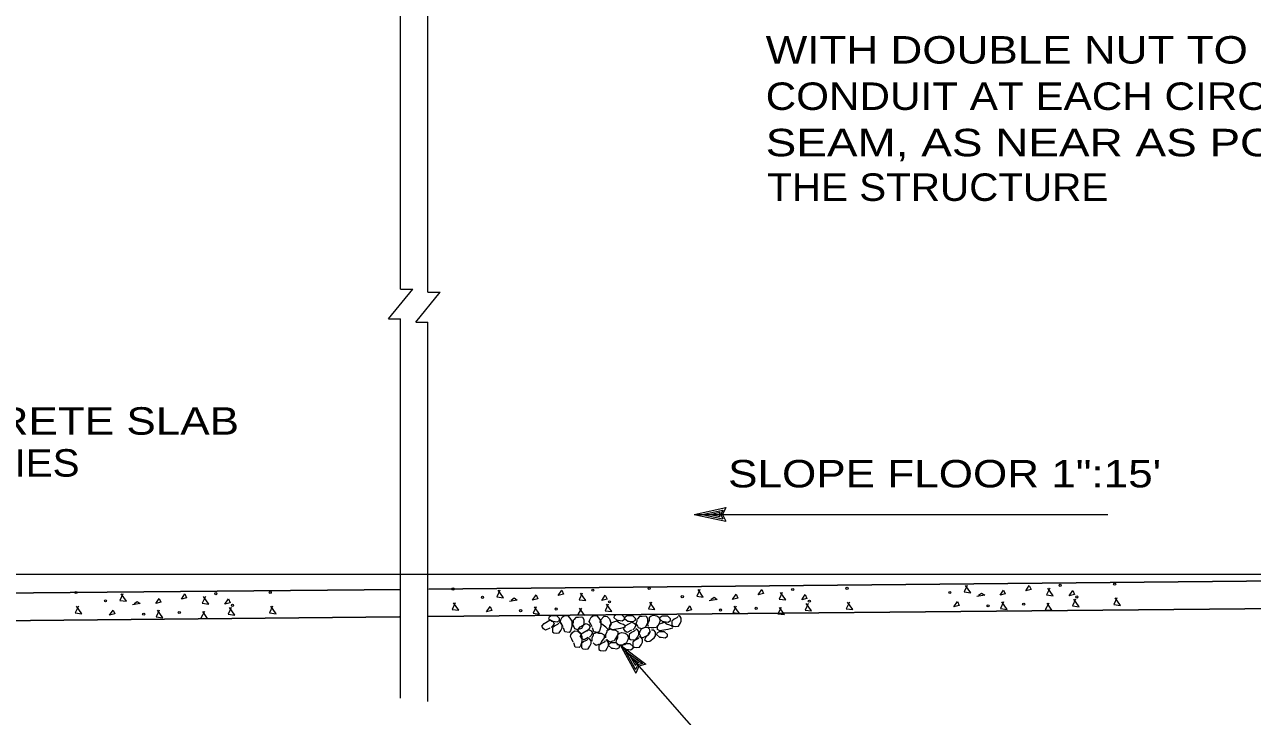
# Model space of a CAD drawing. Extents: x -22.3 to 19.7, y -11.8 to 18.2.
# Drawn here: x -12.72 to -7.13, y -8.18 to -5.03 of the extents above; entities that cross this region are included whole.
import ezdxf
from ezdxf.enums import TextEntityAlignment as Align

# ---------------------------------------------------------------- set-up
doc = ezdxf.new("R2010")
doc.units = 0
doc.header["$LTSCALE"] = 0.05
doc.layers.add('1', color=7, linetype='Continuous', lineweight=13)
doc.layers.add('2', color=7, linetype='Continuous', lineweight=13)

msp = doc.modelspace()

# ---------------------------------------------------------------- linework, layer by layer
at = {"layer": '1'}
for p, q in [((-11.00842, -6.23369), (-11.00842, -4.79569)), ((-10.88342, -6.24869), (-10.88342, -4.81069)), ((-11.06242, -6.36969), (-10.95242, -6.23369)), ((-11.00842, -6.23369), (-10.95242, -6.23369)), ((-10.93742, -6.38469), (-10.82742, -6.24869)), ((-10.88342, -6.24869), (-10.82742, -6.24869)), ((-11.06242, -6.36969), (-11.00842, -6.36969)), ((-11.00842, -8.09569), (-11.00842, -6.36969)), ((-10.93742, -6.38469), (-10.88342, -6.38469)), ((-10.88342, -8.11069), (-10.88342, -6.38469)), ((-9.67142, -7.25969), (-9.52742, -7.22869)), ((-9.67142, -7.25969), (-9.52742, -7.29069)), ((-9.67142, -7.25969), (-7.78742, -7.25969)), ((-9.63442, -7.25969), (-9.54042, -7.23969)), ((-9.63442, -7.25969), (-9.54042, -7.27969)), ((-9.59842, -7.25969), (-9.55342, -7.24969)), ((-9.59842, -7.25969), (-9.55342, -7.26869)), ((-9.55342, -7.24969), (-9.55742, -7.25969)), ((-9.55742, -7.25969), (-9.55342, -7.26869)), ((-9.54042, -7.23969), (-9.54942, -7.25969)), ((-9.54942, -7.25969), (-9.54042, -7.27969)), ((-5.69442, -7.53269), (-18.28242, -7.53269)), ((-10.00842, -7.85269), (-9.89042, -7.94069)), ((-10.00842, -7.85269), (-9.93642, -7.98169)), ((-9.98442, -7.88069), (-9.90642, -7.93769)), ((-9.98442, -7.88069), (-9.93742, -7.96469)), ((-9.96042, -7.90769), (-9.93742, -7.94769)), ((-9.96042, -7.90769), (-9.92342, -7.93469)), ((-9.92342, -7.93469), (-9.93342, -7.93869)), ((-9.90642, -7.93769), (-9.92742, -7.94469)), ((-9.93342, -7.93869), (-9.93742, -7.94769)), ((-9.92742, -7.94469), (-9.93742, -7.96469))]:
    msp.add_line(p, q, dxfattribs=at)
at = {"layer": '1', "lineweight": 25}
for p, q in [((-10.87842, -7.59969), (-3.99142, -7.53369)), ((-16.90342, -7.65769), (-11.00642, -7.60069)), ((-10.88242, -7.72469), (-3.99142, -7.65869)), ((-16.90242, -7.78269), (-11.01242, -7.72569))]:
    msp.add_line(p, q, dxfattribs=at)
at = {"layer": '1'}
for points in [[(-9.52742, -7.22869), (-9.54142, -7.25969), (-9.52742, -7.29069)], [(-10.32842, -7.77669), (-10.34742, -7.78669), (-10.35742, -7.78069), (-10.36442, -7.76869), (-10.35342, -7.75569), (-10.32642, -7.73969), (-10.31442, -7.74569), (-10.30842, -7.75569), (-10.31642, -7.76869), (-10.32242, -7.77469)], [(-10.28742, -7.75469), (-10.29342, -7.76069), (-10.30542, -7.76669), (-10.31642, -7.77569), (-10.31642, -7.78569), (-10.31642, -7.79369), (-10.30942, -7.79869), (-10.29742, -7.80069), (-10.28542, -7.79869), (-10.27842, -7.78769), (-10.27242, -7.77569), (-10.27242, -7.76269), (-10.27842, -7.75469), (-10.28542, -7.75069)], [(-10.26742, -7.77169), (-10.27342, -7.75869), (-10.28042, -7.74669), (-10.27842, -7.73869), (-10.27142, -7.72769), (-10.26142, -7.71969), (-10.24642, -7.72169), (-10.23642, -7.73169), (-10.22842, -7.74469), (-10.22842, -7.76969), (-10.23442, -7.78969), (-10.24042, -7.79669), (-10.25942, -7.79469), (-10.26542, -7.77569)], [(-10.22142, -7.73869), (-10.22142, -7.75169), (-10.22642, -7.75969), (-10.21942, -7.77169), (-10.21542, -7.77869), (-10.20142, -7.78269), (-10.18242, -7.77669), (-10.17242, -7.75769), (-10.17242, -7.74769), (-10.17242, -7.73869), (-10.17842, -7.72869), (-10.18442, -7.72669), (-10.19742, -7.72869), (-10.20942, -7.72869), (-10.21942, -7.73869)], [(-10.16442, -7.79269), (-10.18342, -7.80269), (-10.19342, -7.79669), (-10.20042, -7.78469), (-10.18942, -7.77169), (-10.16242, -7.75569), (-10.15042, -7.76169), (-10.14442, -7.77169), (-10.15242, -7.78469), (-10.15842, -7.79069)], [(-10.13542, -7.77169), (-10.14142, -7.75869), (-10.14842, -7.74669), (-10.14642, -7.73869), (-10.13942, -7.72769), (-10.12942, -7.71969), (-10.11442, -7.72169), (-10.10442, -7.73169), (-10.09642, -7.74469), (-10.09642, -7.76969), (-10.10242, -7.78969), (-10.10842, -7.79669), (-10.12742, -7.79469), (-10.13342, -7.77569)], [(-10.06042, -7.78469), (-10.07242, -7.77269), (-10.09142, -7.75969), (-10.09942, -7.74969), (-10.09742, -7.74069), (-10.08142, -7.72269), (-10.06642, -7.72469), (-10.05642, -7.73469), (-10.05042, -7.75369), (-10.04842, -7.75969), (-10.06042, -7.78069)], [(-9.98542, -7.77269), (-10.00642, -7.77869), (-10.04342, -7.78469), (-10.05442, -7.77869), (-10.05442, -7.76569), (-10.04842, -7.75369), (-10.03142, -7.74769), (-10.02342, -7.74369), (-10.01042, -7.75369), (-10.00442, -7.75569), (-9.99242, -7.75969), (-9.98542, -7.76569), (-9.98542, -7.76769)], [(-9.95642, -7.78669), (-9.97542, -7.79669), (-9.98542, -7.79069), (-9.99242, -7.77869), (-9.98142, -7.76569), (-9.95442, -7.74969), (-9.94242, -7.75569), (-9.93642, -7.76569), (-9.94442, -7.77869), (-9.95042, -7.78469)], [(-9.93142, -7.73469), (-9.93142, -7.74769), (-9.93642, -7.75569), (-9.92942, -7.76769), (-9.92542, -7.77469), (-9.91142, -7.77869), (-9.89242, -7.77269), (-9.88242, -7.75369), (-9.88242, -7.74369), (-9.88242, -7.73469), (-9.88842, -7.72469), (-9.89442, -7.72269), (-9.90742, -7.72469), (-9.91942, -7.72469), (-9.92942, -7.73469)], [(-9.87942, -7.76969), (-9.88142, -7.76169), (-9.87942, -7.74969), (-9.87442, -7.74269), (-9.87442, -7.72669), (-9.86642, -7.72069), (-9.85642, -7.71769), (-9.84142, -7.72069), (-9.83142, -7.72669), (-9.82542, -7.74269), (-9.82942, -7.75169), (-9.83542, -7.76369), (-9.84342, -7.77369), (-9.85442, -7.77569), (-9.86642, -7.77569), (-9.87942, -7.77369)], [(-9.76942, -7.77769), (-9.79042, -7.78369), (-9.82742, -7.78969), (-9.83842, -7.78369), (-9.83842, -7.77069), (-9.83242, -7.75869), (-9.81542, -7.75269), (-9.80742, -7.74869), (-9.79442, -7.75869), (-9.78842, -7.76069), (-9.77642, -7.76469), (-9.76942, -7.77069), (-9.76942, -7.77269)], [(-9.74442, -7.72369), (-9.75042, -7.72969), (-9.76242, -7.73569), (-9.77342, -7.74469), (-9.77342, -7.75469), (-9.77342, -7.76269), (-9.76642, -7.76769), (-9.75442, -7.76969), (-9.74242, -7.76769), (-9.73542, -7.75669), (-9.72942, -7.74469), (-9.72942, -7.73169), (-9.73542, -7.72369), (-9.74242, -7.71969)], [(-10.22142, -7.84069), (-10.22742, -7.82769), (-10.23442, -7.81569), (-10.23242, -7.80769), (-10.22542, -7.79669), (-10.21542, -7.78869), (-10.20042, -7.79069), (-10.19042, -7.80069), (-10.18242, -7.81369), (-10.18242, -7.83869), (-10.18842, -7.85869), (-10.19442, -7.86569), (-10.21342, -7.86369), (-10.21942, -7.84469)], [(-10.15342, -7.81969), (-10.17242, -7.82969), (-10.18242, -7.82369), (-10.18942, -7.81169), (-10.17842, -7.79869), (-10.15142, -7.78269), (-10.13942, -7.78869), (-10.13342, -7.79869), (-10.14142, -7.81169), (-10.14742, -7.81769)], [(-10.15542, -7.82669), (-10.16142, -7.83269), (-10.17342, -7.83869), (-10.18442, -7.84769), (-10.18442, -7.85769), (-10.18442, -7.86569), (-10.17742, -7.87069), (-10.16542, -7.87269), (-10.15342, -7.87069), (-10.14642, -7.85969), (-10.14042, -7.84769), (-10.14042, -7.83469), (-10.14642, -7.82669), (-10.15342, -7.82269)], [(-10.13542, -7.83669), (-10.13542, -7.82669), (-10.13542, -7.82069), (-10.12942, -7.80769), (-10.12942, -7.80169), (-10.12342, -7.79969), (-10.11742, -7.79569), (-10.10642, -7.79969), (-10.09442, -7.79969), (-10.08142, -7.80769), (-10.08142, -7.82069), (-10.09242, -7.83869), (-10.09842, -7.84969), (-10.10642, -7.85169), (-10.11742, -7.85569), (-10.12342, -7.85169), (-10.13142, -7.84369)], [(-10.07242, -7.82169), (-10.07242, -7.81169), (-10.07242, -7.80569), (-10.06642, -7.79269), (-10.06642, -7.78669), (-10.06042, -7.78469), (-10.05442, -7.78069), (-10.04342, -7.78469), (-10.03142, -7.78469), (-10.01842, -7.79269), (-10.01842, -7.80569), (-10.02942, -7.82369), (-10.03542, -7.83469), (-10.04342, -7.83669), (-10.05442, -7.84069), (-10.06042, -7.83669), (-10.06842, -7.82869)], [(-10.02342, -7.84869), (-10.02542, -7.84069), (-10.02342, -7.82869), (-10.01842, -7.82169), (-10.01842, -7.80569), (-10.01042, -7.79969), (-10.00042, -7.79669), (-9.98542, -7.79969), (-9.97542, -7.80569), (-9.96942, -7.82169), (-9.97342, -7.83069), (-9.97942, -7.84269), (-9.98742, -7.85269), (-9.99842, -7.85469), (-10.01042, -7.85469), (-10.02342, -7.85269)], [(-9.93842, -7.78469), (-9.94442, -7.79069), (-9.95642, -7.79669), (-9.96742, -7.80569), (-9.96742, -7.81569), (-9.96742, -7.82369), (-9.96042, -7.82869), (-9.94842, -7.83069), (-9.93642, -7.82869), (-9.92942, -7.81769), (-9.92342, -7.80569), (-9.92342, -7.79269), (-9.92942, -7.78469), (-9.93642, -7.78069)], [(-9.92142, -7.81969), (-9.92742, -7.82569), (-9.93942, -7.83169), (-9.95042, -7.84069), (-9.95042, -7.85069), (-9.95042, -7.85869), (-9.94342, -7.86369), (-9.93142, -7.86569), (-9.91942, -7.86369), (-9.91242, -7.85269), (-9.90642, -7.84069), (-9.90642, -7.82769), (-9.91242, -7.81969), (-9.91942, -7.81569)], [(-9.91342, -7.81569), (-9.91942, -7.80369), (-9.91742, -7.79069), (-9.91142, -7.78069), (-9.89442, -7.77269), (-9.88242, -7.77469), (-9.87542, -7.78069), (-9.87342, -7.79269), (-9.88042, -7.80369), (-9.88242, -7.80969), (-9.89242, -7.81569), (-9.90442, -7.82169), (-9.91742, -7.81769)], [(-9.87142, -7.79369), (-9.87742, -7.80569), (-9.89042, -7.81769), (-9.89642, -7.83069), (-9.88542, -7.83869), (-9.87342, -7.83669), (-9.85242, -7.82069), (-9.84642, -7.81169), (-9.84642, -7.79569), (-9.85442, -7.78669), (-9.86542, -7.78669)], [(-10.07542, -7.83469), (-10.08142, -7.84069), (-10.09342, -7.84669), (-10.10442, -7.85569), (-10.10442, -7.86569), (-10.10442, -7.87369), (-10.09742, -7.87869), (-10.08542, -7.88069), (-10.07342, -7.87869), (-10.06642, -7.86769), (-10.06042, -7.85569), (-10.06042, -7.84269), (-10.06642, -7.83469), (-10.07342, -7.83069)], [(-10.00842, -7.85269), (-9.50042, -8.43069), (-9.26142, -8.43069)], [(-9.89042, -7.94069), (-9.92242, -7.95069), (-9.93642, -7.98169)]]:
    msp.add_lwpolyline(points, dxfattribs=at)
for points in [[(-10.33342, -7.73369), (-10.31942, -7.74569), (-10.31242, -7.74569), (-10.29442, -7.74869), (-10.28342, -7.74169), (-10.28342, -7.73369), (-10.29642, -7.72169), (-10.30642, -7.72169), (-10.32142, -7.72169), (-10.33142, -7.72769)], [(-10.03742, -7.72869), (-10.02342, -7.74069), (-10.01642, -7.74069), (-9.99842, -7.74369), (-9.98742, -7.73669), (-9.98742, -7.72869), (-10.00042, -7.71669), (-10.01042, -7.71669), (-10.02542, -7.71669), (-10.03542, -7.72269)], [(-9.98742, -7.73269), (-9.97342, -7.74469), (-9.96642, -7.74469), (-9.94842, -7.74769), (-9.93742, -7.74069), (-9.93742, -7.73269), (-9.95042, -7.72069), (-9.96042, -7.72069), (-9.97542, -7.72069), (-9.98542, -7.72669)], [(-9.82842, -7.73469), (-9.81442, -7.74669), (-9.80742, -7.74669), (-9.78942, -7.74969), (-9.77842, -7.74269), (-9.77842, -7.73469), (-9.79142, -7.72269), (-9.80142, -7.72269), (-9.81642, -7.72269), (-9.82642, -7.72869)], [(-9.84242, -7.80569), (-9.82842, -7.81769), (-9.82142, -7.81769), (-9.80342, -7.82069), (-9.79242, -7.81369), (-9.79242, -7.80569), (-9.80542, -7.79369), (-9.81542, -7.79369), (-9.83042, -7.79369), (-9.84042, -7.79969)], [(-10.06142, -7.85669), (-10.04742, -7.86869), (-10.04042, -7.86869), (-10.02242, -7.87169), (-10.01142, -7.86469), (-10.01142, -7.85669), (-10.02442, -7.84469), (-10.03442, -7.84469), (-10.04942, -7.84469), (-10.05942, -7.85069)], [(-9.99942, -7.86069), (-9.98542, -7.87269), (-9.97842, -7.87269), (-9.96042, -7.87569), (-9.94942, -7.86869), (-9.94942, -7.86069), (-9.96242, -7.84869), (-9.97242, -7.84869), (-9.98742, -7.84869), (-9.99742, -7.85469)]]:
    msp.add_lwpolyline(points, close=True, dxfattribs=at)
at = {"layer": '2'}
for points in [[(-9.64542, -7.60169), (-9.65942, -7.63169), (-9.62942, -7.63569), (-9.65342, -7.60169)], [(-8.42742, -7.58269), (-8.44142, -7.61269), (-8.41142, -7.61669), (-8.43542, -7.58269)], [(-8.05242, -7.59569), (-8.06642, -7.62569), (-8.03642, -7.62969), (-8.06042, -7.59569)], [(-12.27142, -7.62069), (-12.28542, -7.65069), (-12.25542, -7.65469), (-12.27942, -7.62069)], [(-12.22042, -7.66569), (-12.20642, -7.65569), (-12.19242, -7.66569), (-12.22842, -7.67169)], [(-11.89642, -7.63369), (-11.91042, -7.66369), (-11.88042, -7.66769), (-11.90442, -7.63369)], [(-10.55542, -7.60469), (-10.56942, -7.63469), (-10.53942, -7.63869), (-10.56342, -7.60469)], [(-10.50442, -7.64969), (-10.49042, -7.63969), (-10.47642, -7.64969), (-10.51242, -7.65569)], [(-10.18042, -7.61769), (-10.19442, -7.64769), (-10.16442, -7.65169), (-10.18842, -7.61769)], [(-9.59442, -7.64669), (-9.58042, -7.63669), (-9.56642, -7.64669), (-9.60242, -7.65269)], [(-9.27042, -7.61469), (-9.28442, -7.64469), (-9.25442, -7.64869), (-9.27842, -7.61469)], [(-8.37642, -7.62769), (-8.36242, -7.61769), (-8.34842, -7.62769), (-8.38442, -7.63369)], [(-8.26242, -7.65769), (-8.27642, -7.68769), (-8.24642, -7.69169), (-8.27042, -7.65769)], [(-7.93442, -7.64569), (-7.94842, -7.67569), (-7.91842, -7.67969), (-7.94242, -7.64569)], [(-7.74642, -7.63969), (-7.76042, -7.66969), (-7.73042, -7.67369), (-7.75442, -7.63969)], [(-12.47442, -7.67769), (-12.48842, -7.70769), (-12.45842, -7.71169), (-12.48242, -7.67769)], [(-12.10642, -7.69569), (-12.12042, -7.72569), (-12.09042, -7.72969), (-12.11442, -7.69569)], [(-11.90042, -7.70169), (-11.91642, -7.73169), (-11.88642, -7.73369), (-11.90842, -7.70169)], [(-11.77842, -7.68369), (-11.79242, -7.71369), (-11.76242, -7.71769), (-11.78642, -7.68369)], [(-11.59042, -7.67769), (-11.60442, -7.70769), (-11.57442, -7.71169), (-11.59842, -7.67769)], [(-10.75842, -7.66169), (-10.77242, -7.69169), (-10.74242, -7.69569), (-10.76642, -7.66169)], [(-10.39042, -7.67969), (-10.40442, -7.70969), (-10.37442, -7.71369), (-10.39842, -7.67969)], [(-10.18442, -7.68569), (-10.20042, -7.71569), (-10.17042, -7.71769), (-10.19242, -7.68569)], [(-10.06242, -7.66769), (-10.07642, -7.69769), (-10.04642, -7.70169), (-10.07042, -7.66769)], [(-9.86542, -7.65869), (-9.87942, -7.68869), (-9.84942, -7.69269), (-9.87342, -7.65869)], [(-9.48042, -7.67669), (-9.49442, -7.70669), (-9.46442, -7.71069), (-9.48842, -7.67669)], [(-9.27442, -7.68269), (-9.29042, -7.71269), (-9.26042, -7.71469), (-9.28242, -7.68269)], [(-9.15242, -7.66469), (-9.16642, -7.69469), (-9.13642, -7.69869), (-9.16042, -7.66469)], [(-8.96442, -7.65869), (-8.97842, -7.68869), (-8.94842, -7.69269), (-8.97242, -7.65869)], [(-8.05642, -7.66369), (-8.07242, -7.69369), (-8.04242, -7.69569), (-8.06442, -7.66369)]]:
    msp.add_lwpolyline(points, dxfattribs=at)
for points in [[(-9.37942, -7.62569), (-9.36342, -7.60169), (-9.35542, -7.61969)], [(-8.16142, -7.60669), (-8.14542, -7.58269), (-8.13742, -7.60069)], [(-12.12242, -7.66569), (-12.10642, -7.64169), (-12.09842, -7.65969)], [(-12.00542, -7.64469), (-11.98942, -7.62069), (-11.98142, -7.63869)], [(-11.80742, -7.66769), (-11.79142, -7.64369), (-11.78342, -7.66169)], [(-10.40642, -7.64969), (-10.39042, -7.62569), (-10.38242, -7.64369)], [(-10.28942, -7.62869), (-10.27342, -7.60469), (-10.26542, -7.62269)], [(-10.09142, -7.65169), (-10.07542, -7.62769), (-10.06742, -7.64569)], [(-9.49642, -7.64669), (-9.48042, -7.62269), (-9.47242, -7.64069)], [(-9.18142, -7.64869), (-9.16542, -7.62469), (-9.15742, -7.64269)], [(-8.48842, -7.68069), (-8.47242, -7.65669), (-8.46442, -7.67469)], [(-8.27842, -7.62769), (-8.26242, -7.60369), (-8.25442, -7.62169)], [(-7.96342, -7.62969), (-7.94742, -7.60569), (-7.93942, -7.62369)], [(-12.33242, -7.71869), (-12.31642, -7.69469), (-12.30842, -7.71269)], [(-10.61642, -7.70269), (-10.60042, -7.67869), (-10.59242, -7.69669)], [(-9.70642, -7.69969), (-9.69042, -7.67569), (-9.68242, -7.69369)]]:
    msp.add_lwpolyline(points, close=True, dxfattribs=at)
for centre in [(-10.76892, -7.59881), (-10.13242, -7.60406), (-9.87592, -7.59581), (-9.22242, -7.60106), (-8.97492, -7.59581), (-8.00442, -7.58206), (-7.75692, -7.57681), (-12.48492, -7.61481), (-12.35092, -7.65306), (-11.84842, -7.62006), (-11.60092, -7.61481), (-10.63492, -7.63706), (-10.05667, -7.65731), (-9.72492, -7.63406), (-9.14667, -7.65431), (-8.50692, -7.61506), (-7.92867, -7.63531), (-12.17692, -7.71381), (-12.01492, -7.70631), (-11.77267, -7.67331), (-10.46092, -7.69781), (-10.29892, -7.69031), (-9.55092, -7.69481), (-9.38892, -7.68731), (-8.33292, -7.67581), (-8.17092, -7.66831)]:
    msp.add_circle(centre, 0.00487, dxfattribs=at)

# ---------------------------------------------------------------- texts
at = {"layer": '1'}
for s, width, p in [('WITH DOUBLE NUT TO CARRY ELECTRICAL', 1.2, (-9.34542, -5.20769)), ('CONDUIT AT EACH CIRCUMFERENTIAL', 1.15, (-9.34542, -5.41869)), ('SEAM, AS NEAR AS POSSIBLE TO THE C OF', 1.25, (-9.34542, -5.62969)), ('THE STRUCTURE', 1.1, (-9.33842, -5.83269)), ('TOP OF CONCRETE SLAB', 1.2, (-14.23942, -6.89669)), ('SLOPE FLOOR 1":15\'', 1.2, (-9.51642, -7.13669))]:
    msp.add_text(s, height=0.125, dxfattribs=dict(at, width=width)).set_placement(p)
at = {"layer": '1', "width": 1.1}
msp.add_text('ELEV. VARIES', height=0.125, dxfattribs=at).set_placement((-13.09242, -7.08769), align=Align.CENTER)

doc.saveas('drawing.dxf')
